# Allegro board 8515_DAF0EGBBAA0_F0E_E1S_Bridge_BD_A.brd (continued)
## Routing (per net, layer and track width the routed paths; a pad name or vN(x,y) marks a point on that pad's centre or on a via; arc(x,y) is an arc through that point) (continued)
DELTA_L_85_5INCH_TOP_DN: length 127
  TOP w0.132: J8.2 -14.43,31.48 -14.43,34.71 -14.64,35.89 -15.7,37.42 -18.96,38 -19.2,38.35 -19.08,39.03 -18.73,39.28 -14.55,38.54 -13.97,38.95 -13.8,39.91 -14.21,40.49 -19.01,41.34 -19.21,41.63 -19.08,42.36 -18.73,42.61 -14.55,41.87 -13.97,42.28 -13.8,43.23 -13.89,43.37 -13.95,43.46 -14.21,43.82 -18.92,44.65 -19.2,45.05 -19.08,45.69 -18.73,45.94 -16.65,45.57 -16.64,45.57 -14.55,45.2 -13.97,45.61 -13.88,46.09 -13.8,46.56 -14.21,47.15 -18.95,47.99 -19.2,48.35 -19.08,49.02 -18.73,49.27 -14.55,48.53 -13.97,48.94 -13.8,49.89 -14.21,50.48 -18.95,51.32 -19.2,51.68 -19.08,52.35 -18.73,52.6 -18.7,52.59 -14.55,51.86 -13.97,52.27 -13.8,53.22 -14.21,53.81 -18.96,54.65 -19.21,54.99 -19.08,55.68 -18.73,55.93 -14.55,55.19 -13.97,55.6 -13.8,56.55 -14.21,57.14 -18.96,57.98 -19.2,58.33 -19.09,59.01 -18.73,59.26 -14.55,58.52 -13.97,58.93 -13.8,59.88 -14.21,60.47 -18.97,61.31 -19.21,61.64 -19.08,62.34 -18.73,62.58 -14.54,61.85 -13.94,62.27 -13.8,63.09 -14.3,63.81 -18.98,64.64 -19.21,64.97 -19.08,65.7 -18.92,65.81 -18.76,65.92 -15.76,65.39 -14.66,66.16 -14.43,67.45 -14.43,72.53 J9.1
DELTA_L_85_5INCH_TOP_DP: length 127
  TOP w0.132: J8.1 -14.77,31.48 -14.77,34.68 -14.96,35.76 -15.9,37.11 -19.16,37.69 -19.56,38.27 -19.4,39.23 -18.81,39.64 -14.63,38.9 -14.28,39.15 -14.16,39.83 -14.4,40.18 -19.2,41.03 -19.57,41.55 -19.4,42.56 -18.81,42.97 -14.63,42.23 -14.28,42.48 -14.16,43.16 -14.4,43.51 -19.12,44.34 -19.56,44.97 -19.4,45.89 -18.81,46.3 -16.59,45.91 -16.58,45.9 -14.63,45.56 -14.28,45.81 -14.16,46.48 -14.4,46.84 -19.15,47.68 -19.56,48.27 -19.4,49.22 -18.81,49.63 -16.58,49.23 -14.63,48.89 -14.28,49.14 -14.16,49.81 -14.4,50.17 -19.15,51.01 -19.56,51.6 -19.4,52.55 -18.81,52.96 -18.53,52.91 -18.53,52.91 -14.63,52.22 -14.28,52.47 -14.16,53.14 -14.4,53.5 -19.16,54.34 -19.57,54.92 -19.4,55.88 -18.81,56.29 -14.63,55.55 -14.28,55.8 -14.16,56.47 -14.4,56.83 -19.16,57.66 -19.56,58.25 -19.4,59.21 -18.81,59.62 -14.63,58.88 -14.28,59.12 -14.16,59.8 -14.4,60.15 -19.17,61 -19.57,61.56 -19.4,62.53 -18.81,62.94 -14.62,62.21 -14.26,62.46 -14.16,63.02 -14.5,63.5 -19.17,64.33 -19.57,64.89 -19.54,65.03 -19.39,65.89 -18.84,66.28 -15.84,65.75 -14.97,66.36 -14.77,67.48 -14.77,72.53 J9.2
DELTA_L_85_10INCH_BOT_DN: length 254
  BOTTOM w0.132: J21.1 -20.16,102.88 -20.16,97.17 -20.36,96.04 -20.9,95.66 -24.28,96.25 -24.88,95.8 -25.05,94.85 -24.68,94.31 -19.69,93.43 -19.44,93.08 -19.56,92.4 -19.74,92.28 -19.74,92.27 -19.91,92.15 -24.29,92.92 -25,92.43 -25.14,91.64 -24.68,90.98 -19.69,90.1 -19.44,89.75 -19.56,89.07 -19.91,88.82 -24.33,89.6 -24.94,89.18 -25.1,88.28 -24.66,87.65 -19.69,86.77 -19.44,86.42 -19.56,85.74 -19.91,85.49 -23.86,86.19 -24.34,86.28 -24.93,85.87 -25.1,84.91 -24.69,84.33 -19.69,83.44 -19.44,83.09 -19.56,82.41 -19.91,82.16 -24.41,82.96 -24.92,82.6 -25.1,81.58 -24.69,81 -19.69,80.11 -19.44,79.76 -19.56,79.08 -19.91,78.83 -23.98,79.55 -24.41,79.63 -24.92,79.27 -25.1,78.23 -24.71,77.67 -19.69,76.78 -19.44,76.43 -19.5,76.09 -19.56,75.75 -19.91,75.51 -24.41,76.3 -24.92,75.94 -25.1,74.96 -24.66,74.33 -19.69,73.45 -19.44,73.1 -19.56,72.42 -19.91,72.18 -24.36,72.96 -24.93,72.56 -25.11,71.54 -24.74,71.02 -19.69,70.12 -19.44,69.77 -19.56,69.09 -19.91,68.85 -24.38,69.64 -24.93,69.25 -25.1,68.28 -24.67,67.68 -19.69,66.8 -19.44,66.44 -19.56,65.76 -19.91,65.52 -24.34,66.3 -24.93,65.88 -25.09,65.01 -24.62,64.34 -19.69,63.47 -19.44,63.11 -19.5,62.77 -19.56,62.44 -19.91,62.19 -24.43,62.99 -24.92,62.65 -25.1,61.64 -24.66,61.01 -19.69,60.14 -19.44,59.78 -19.56,59.11 -19.91,58.86 -24.33,59.64 -24.94,59.21 -25.1,58.31 -24.66,57.69 -19.69,56.81 -19.44,56.45 -19.56,55.78 -19.56,55.78 -19.91,55.53 -24.3,56.3 -24.94,55.85 -25.09,55.02 -24.62,54.35 -19.69,53.48 -19.44,53.12 -19.5,52.79 -19.56,52.45 -19.91,52.2 -24.32,52.98 -24.89,52.58 -25.06,51.64 -24.62,51.02 -19.69,50.15 -19.44,49.8 -19.5,49.46 -19.56,49.12 -19.91,48.87 -24.3,49.64 -24.86,49.25 -25.03,48.26 -24.63,47.69 -19.69,46.82 -19.44,46.47 -19.56,45.79 -19.91,45.54 -24.25,46.31 -24.88,45.86 -25.04,44.98 -24.61,44.36 -19.69,43.49 -19.44,43.14 -19.5,42.8 -19.56,42.46 -19.91,42.21 -24.42,43.01 -24.94,42.64 -25.11,41.66 -24.68,41.04 -19.69,40.16 -19.44,39.81 -19.56,39.13 -19.91,38.88 -24.68,39.72 -25.12,39.41 -25.32,38.29 -24.95,37.76 -21.17,37.09 -20.38,35.96 -20.16,34.68 -20.16,31.48 J22.2
DELTA_L_85_10INCH_BOT_DP: length 254
  BOTTOM w0.132: J22.1 -19.82,31.48 -19.82,34.71 -20.06,36.09 -20.97,37.4 -24.75,38.07 -24.96,38.37 -24.81,39.22 -24.6,39.36 -19.83,38.52 -19.25,38.93 -19.08,39.89 -19.49,40.47 -24.48,41.35 -24.75,41.74 -24.63,42.45 -24.34,42.65 -19.83,41.85 -19.25,42.26 -19.08,43.22 -19.49,43.8 -24.41,44.67 -24.68,45.06 -24.57,45.67 -24.17,45.95 -19.83,45.18 -19.54,45.39 -19.25,45.59 -19.08,46.55 -19.49,47.13 -24.43,48 -24.67,48.34 -24.54,49.05 -24.22,49.28 -19.83,48.51 -19.25,48.92 -19.08,49.87 -19.49,50.46 -24.42,51.33 -24.7,51.72 -24.58,52.38 -24.24,52.62 -19.83,51.84 -19.54,52.04 -19.25,52.25 -19.08,53.2 -19.49,53.79 -24.42,54.66 -24.73,55.1 -24.63,55.66 -24.22,55.94 -19.83,55.17 -19.25,55.58 -19.25,55.58 -19.08,56.53 -19.49,57.12 -24.46,58 -24.74,58.39 -24.63,59.01 -24.25,59.28 -19.83,58.5 -19.25,58.91 -19.08,59.86 -19.49,60.45 -24.46,61.33 -24.74,61.72 -24.61,62.45 -24.35,62.63 -19.83,61.83 -19.25,62.24 -19.08,63.19 -19.49,63.78 -24.42,64.65 -24.73,65.09 -24.62,65.69 -24.26,65.94 -19.83,65.16 -19.25,65.57 -19.08,66.52 -19.49,67.11 -24.47,67.99 -24.74,68.36 -24.62,69.05 -24.3,69.28 -19.83,68.49 -19.25,68.9 -19.08,69.85 -19.49,70.44 -24.55,71.33 -24.75,71.62 -24.62,72.36 -24.28,72.6 -19.83,71.82 -19.25,72.23 -19.08,73.18 -19.49,73.76 -24.46,74.64 -24.74,75.04 -24.61,75.74 -24.33,75.94 -19.83,75.15 -19.25,75.55 -19.08,76.51 -19.49,77.09 -24.51,77.98 -24.74,78.31 -24.61,79.08 -24.33,79.27 -19.83,78.47 -19.25,78.88 -19.08,79.84 -19.49,80.42 -24.49,81.31 -24.74,81.66 -24.61,82.4 -24.33,82.6 -19.83,81.8 -19.25,82.21 -19.08,83.17 -19.49,83.75 -24.49,84.64 -24.74,84.99 -24.62,85.67 -24.26,85.92 -19.83,85.13 -19.25,85.54 -19.08,86.5 -19.49,87.08 -24.46,87.96 -24.74,88.36 -24.63,88.98 -24.25,89.24 -19.83,88.46 -19.25,88.87 -19.08,89.83 -19.49,90.41 -24.48,91.29 -24.78,91.72 -24.69,92.23 -24.21,92.56 -19.83,91.79 -19.25,92.2 -19.08,93.16 -19.49,93.74 -24.48,94.62 -24.69,94.92 -24.57,95.61 -24.19,95.89 -20.82,95.3 -20.05,95.84 -19.82,97.14 -19.82,102.88 J21.2
DELTA_L_85_10INCH_IN1_DN: length 254
  IN1 w0.155: v3(-24.69,102.52) -24.89,102.32 -24.89,96.85 -25.42,96.08 -26.43,95.38 -29.25,95.88 -29.57,95.66 -29.69,94.96 -29.44,94.61 -24.4,93.72 -23.97,93.1 -24.14,92.1 -24.66,91.74 -29.43,92.58 -29.78,92.33 -29.88,91.75 -29.57,91.3 -24.56,90.42 -24.24,89.95 -24.15,89.83 -24.32,88.87 -24.91,88.45 -27.13,88.84 -29.35,89.24 -29.75,88.95 -29.85,88.38 -29.57,87.97 -24.54,87.09 -24.14,86.52 -24.32,85.53 -24.9,85.12 -29.35,85.91 -29.69,85.66 -29.81,84.99 -29.57,84.64 -24.56,83.76 -24.15,83.17 -24.35,82.07 -24.77,81.77 -29.35,82.58 -29.69,82.33 -29.81,81.66 -29.57,81.32 -24.56,80.43 -24.15,79.84 -24.33,78.84 -24.88,78.46 -29.35,79.25 -29.69,79 -29.81,78.33 -29.57,77.99 -24.56,77.1 -24.15,76.51 -24.32,75.55 -24.91,75.14 -29.35,75.92 -29.69,75.68 -29.81,75 -29.57,74.66 -24.56,73.77 -24.15,73.18 -24.32,72.22 -24.91,71.81 -29.35,72.59 -29.69,72.35 -29.81,71.67 -29.57,71.33 -24.56,70.44 -24.15,69.85 -24.32,68.89 -24.91,68.48 -29.35,69.26 -29.69,69.02 -29.81,68.35 -29.57,68 -24.56,67.11 -24.15,66.52 -24.32,65.56 -24.91,65.15 -29.35,65.93 -29.69,65.69 -29.81,65.02 -29.57,64.67 -24.56,63.79 -24.15,63.19 -24.32,62.23 -24.91,61.82 -29.35,62.6 -29.69,62.36 -29.81,61.69 -29.57,61.34 -24.56,60.46 -24.15,59.87 -24.32,58.9 -24.91,58.49 -29.35,59.27 -29.69,59.03 -29.81,58.36 -29.57,58.01 -24.63,57.14 -24.16,56.47 -24.3,55.7 -25.03,55.18 -29.35,55.94 -29.69,55.7 -29.81,55.03 -29.57,54.68 -24.56,53.8 -24.15,53.21 -24.32,52.24 -24.91,51.83 -29.35,52.61 -29.69,52.37 -29.81,51.7 -29.57,51.35 -24.56,50.47 -24.15,49.88 -24.32,48.92 -24.91,48.5 -29.35,49.28 -29.69,49.04 -29.81,48.37 -29.57,48.02 -24.56,47.14 -24.15,46.55 -24.32,45.59 -24.91,45.17 -29.35,45.96 -29.69,45.71 -29.81,45.04 -29.57,44.69 -24.56,43.81 -24.15,43.22 -24.32,42.26 -24.91,41.84 -29.35,42.63 -29.69,42.38 -29.79,41.82 -29.46,41.35 -24.5,40.47 -24.1,39.89 -24.26,38.97 -24.87,38.55 -29.41,39.36 -29.75,39.12 -29.88,38.37 -29.63,38.04 -26.33,37.45 -26.22,37.43 -25.34,36.56 -25.25,36.5 -25.23,36.45 -25.09,35.85 -24.92,35.12 -24.89,35.09 -24.89,32.04 v3(-24.69,31.85)
  BOTTOM w0.132: J24.2 v3(-24.69,102.52) ; J23.1 v3(-24.69,31.85)
DELTA_L_85_10INCH_IN1_DP: length 254
  IN1 w0.155: v3(-25.44,31.85) -25.25,32.04 -25.25,34.94 -25.44,35.77 -25.56,36.27 -26.4,37.1 -29.83,37.71 -30.27,38.27 -30.08,39.33 -29.49,39.74 -24.95,38.93 -24.59,39.18 -24.48,39.81 -24.71,40.14 -29.67,41.02 -30.17,41.74 -30.02,42.59 -29.43,43 -25,42.22 -24.65,42.47 -24.53,43.14 -24.77,43.48 -29.78,44.37 -30.19,44.96 -30.02,45.92 -29.43,46.33 -25,45.55 -24.65,45.79 -24.53,46.46 -24.77,46.81 -29.78,47.7 -30.19,48.29 -30.02,49.25 -29.43,49.66 -25,48.88 -24.65,49.12 -24.53,49.79 -24.77,50.14 -29.78,51.02 -30.19,51.62 -30.02,52.58 -29.43,52.99 -25,52.21 -24.65,52.45 -24.53,53.12 -24.77,53.47 -29.78,54.35 -30.19,54.94 -30.02,55.91 -29.43,56.32 -25.12,55.56 -24.63,55.9 -24.54,56.38 -24.84,56.81 -29.78,57.68 -30.19,58.27 -30.02,59.24 -29.43,59.65 -25,58.87 -24.65,59.11 -24.53,59.78 -24.77,60.13 -29.78,61.01 -30.19,61.6 -30.02,62.57 -29.43,62.98 -25,62.2 -24.65,62.44 -24.53,63.11 -24.77,63.46 -29.78,64.34 -30.19,64.93 -30.02,65.9 -29.43,66.31 -25,65.53 -24.65,65.77 -24.53,66.44 -24.77,66.79 -29.78,67.67 -30.19,68.26 -30.02,69.23 -29.43,69.64 -25,68.86 -24.65,69.1 -24.53,69.77 -24.77,70.12 -29.78,71 -30.19,71.59 -30.02,72.55 -29.43,72.97 -25,72.19 -24.65,72.43 -24.53,73.1 -24.77,73.45 -29.78,74.33 -30.19,74.92 -30.02,75.88 -29.43,76.3 -25,75.51 -24.65,75.76 -24.53,76.43 -24.77,76.78 -29.78,77.66 -30.19,78.25 -30.02,79.21 -29.43,79.63 -24.96,78.84 -24.65,79.05 -24.53,79.76 -24.77,80.1 -29.78,80.99 -30.19,81.58 -30.02,82.54 -29.43,82.96 -24.85,82.15 -24.67,82.27 -24.53,83.09 -24.77,83.43 -29.78,84.32 -30.19,84.91 -30.17,85.05 -30.02,85.87 -29.43,86.29 -24.99,85.5 -24.65,85.74 -24.52,86.43 -24.75,86.76 -29.78,87.65 -30.23,88.29 -30.08,89.16 -29.43,89.62 -25,88.83 -24.65,89.08 -24.53,89.74 -24.77,90.09 -29.78,90.98 -30.26,91.67 -30.11,92.54 -29.51,92.96 -24.75,92.12 -24.47,92.31 -24.35,93.01 -24.61,93.39 -29.65,94.28 -30.07,94.88 -29.89,95.87 -29.33,96.26 -26.51,95.76 -25.68,96.34 -25.25,96.96 -25.25,102.32 v3(-25.44,102.52)
  BOTTOM w0.132: J23.2 v3(-25.44,31.85) ; J24.1 v3(-25.44,102.52)
DELTA_L_85_10INCH_IN2_DN: length 254
  TOP w0.132: J26.2 v3(-22.9,102.52) ; J25.1 v3(-22.9,31.85)
  IN2 w0.155: v3(-22.9,31.85) -22.71,32.04 -22.71,34.95 -22.93,36.21 -23.51,37.05 -27.38,37.73 -27.59,38.03 -27.84,38.4 -27.68,39.29 -27.08,39.71 -22.57,38.91 -22.09,39.25 -21.99,39.81 -22.23,40.15 -27.24,41.04 -27.65,41.63 -27.48,42.59 -26.89,43 -22.46,42.22 -22.11,42.47 -21.99,43.14 -22.23,43.48 -27.24,44.37 -27.65,44.96 -27.48,45.92 -26.89,46.33 -22.46,45.55 -22.11,45.79 -21.99,46.46 -22.23,46.81 -27.24,47.7 -27.65,48.29 -27.48,49.25 -26.89,49.66 -22.46,48.88 -22.11,49.12 -21.99,49.79 -22.23,50.14 -27.24,51.02 -27.65,51.62 -27.48,52.58 -26.89,52.99 -22.46,52.21 -22.11,52.45 -21.99,53.12 -22.23,53.47 -27.24,54.35 -27.65,54.94 -27.48,55.91 -26.89,56.32 -22.43,55.53 -22.11,55.76 -21.99,56.45 -22.23,56.8 -27.24,57.68 -27.65,58.27 -27.48,59.24 -26.89,59.65 -22.46,58.87 -22.11,59.11 -21.99,59.78 -22.23,60.13 -27.24,61.01 -27.65,61.6 -27.48,62.57 -26.89,62.98 -22.46,62.2 -22.11,62.44 -21.99,63.11 -22.23,63.46 -27.24,64.34 -27.65,64.93 -27.48,65.9 -26.89,66.31 -22.46,65.53 -22.11,65.77 -21.99,66.44 -22.23,66.79 -27.24,67.67 -27.65,68.26 -27.48,69.23 -26.89,69.64 -22.46,68.86 -22.11,69.1 -21.99,69.77 -22.23,70.12 -27.24,71 -27.65,71.59 -27.48,72.55 -26.89,72.97 -22.46,72.19 -22.11,72.43 -21.99,73.1 -22.23,73.45 -27.24,74.33 -27.65,74.92 -27.48,75.88 -26.89,76.3 -22.46,75.51 -22.11,75.76 -21.99,76.43 -22.23,76.78 -27.24,77.66 -27.65,78.25 -27.48,79.21 -27.01,79.54 -26.89,79.63 -22.47,78.85 -22.1,79.11 -21.99,79.73 -22.26,80.11 -27.24,80.99 -27.65,81.58 -27.51,82.37 -27.51,82.52 -27.25,82.7 -26.89,82.96 -26.73,82.93 -26.05,82.81 -25.97,82.8 -25.87,82.79 -25.76,82.77 -22.45,82.22 -22.09,82.52 -21.99,83.06 -22.26,83.44 -27.24,84.32 -27.65,84.91 -27.48,85.87 -26.89,86.29 -22.48,85.51 -22.1,85.77 -21.98,86.45 -22.2,86.76 -27.24,87.65 -27.65,88.24 -27.48,89.2 -26.89,89.62 -22.46,88.83 -22.11,89.08 -21.99,89.74 -22.23,90.09 -27.24,90.98 -27.65,91.57 -27.57,92.05 -27.48,92.53 -26.9,92.94 -22.5,92.17 -22.14,92.37 -22,93.18 -22.16,93.41 -27.24,94.31 -27.65,94.9 -27.59,95.22 -27.59,95.24 -27.57,95.37 -27.54,95.5 -27.54,95.53 -27.53,95.59 -27.51,95.71 -27.5,95.76 -27.43,95.89 -27.28,96 -27.01,96.19 -26.89,96.27 -23.6,95.7 -22.88,96.34 -22.71,97.34 -22.71,102.32 v3(-22.9,102.52)
DELTA_L_85_10INCH_IN2_DP: length 254
  TOP w0.132: J25.2 v3(-22.15,31.85) ; J26.1 v3(-22.15,102.52)
  IN2 w0.155: v3(-22.15,31.85) -22.35,32.04 -22.35,34.98 -22.59,36.35 -23.3,37.38 -27.17,38.06 -27.29,38.23 -27.46,38.48 -27.35,39.08 -26.99,39.33 -22.49,38.53 -21.76,39.04 -21.61,39.89 -22.02,40.48 -27.03,41.36 -27.27,41.71 -27.15,42.38 -26.81,42.63 -22.37,41.84 -21.78,42.26 -21.61,43.22 -22.02,43.81 -27.03,44.69 -27.27,45.04 -27.15,45.71 -26.81,45.96 -22.37,45.17 -21.78,45.59 -21.61,46.55 -22.02,47.14 -27.03,48.02 -27.27,48.37 -27.15,49.04 -26.81,49.28 -22.37,48.5 -21.78,48.92 -21.61,49.88 -22.02,50.47 -27.03,51.35 -27.27,51.7 -27.15,52.37 -26.81,52.61 -22.37,51.83 -21.78,52.24 -21.61,53.21 -22.02,53.8 -27.03,54.68 -27.27,55.03 -27.15,55.7 -26.81,55.94 -22.35,55.16 -21.78,55.55 -21.61,56.54 -22.02,57.13 -27.03,58.01 -27.27,58.36 -27.15,59.03 -26.81,59.27 -22.37,58.49 -21.78,58.9 -21.61,59.87 -22.02,60.46 -27.03,61.34 -27.27,61.69 -27.15,62.36 -26.81,62.6 -22.37,61.82 -21.78,62.23 -21.61,63.19 -22.02,63.79 -27.03,64.67 -27.27,65.02 -27.15,65.69 -26.81,65.93 -22.37,65.15 -21.78,65.56 -21.61,66.52 -22.02,67.11 -27.03,68 -27.27,68.35 -27.15,69.02 -26.81,69.26 -22.37,68.48 -21.78,68.89 -21.61,69.85 -22.02,70.44 -27.03,71.33 -27.27,71.67 -27.15,72.35 -26.81,72.59 -22.37,71.81 -21.78,72.22 -21.61,73.18 -22.02,73.77 -27.03,74.66 -27.27,75 -27.15,75.68 -26.81,75.92 -22.37,75.14 -21.78,75.55 -21.61,76.51 -22.02,77.1 -27.03,77.99 -27.27,78.33 -27.15,79 -26.81,79.25 -22.39,78.47 -21.78,78.9 -21.62,79.81 -22.05,80.44 -27.03,81.32 -27.27,81.66 -27.15,82.33 -26.97,82.46 -26.81,82.58 -26.77,82.57 -26.76,82.57 -26.11,82.46 -26.03,82.45 -25.81,82.41 -25.81,82.41 -22.34,81.84 -21.76,82.33 -21.61,83.15 -22.05,83.77 -27.03,84.64 -27.27,84.99 -27.15,85.66 -26.81,85.91 -22.39,85.13 -21.78,85.56 -21.6,86.54 -21.99,87.08 -27.03,87.97 -27.27,88.32 -27.15,88.99 -26.81,89.24 -22.37,88.45 -21.78,88.87 -21.61,89.83 -22.02,90.42 -27.03,91.3 -27.27,91.65 -27.15,92.32 -26.81,92.56 -22.44,91.79 -21.82,92.14 -21.62,93.26 -21.96,93.74 -27.03,94.63 -27.27,94.98 -27.24,95.16 -27.24,95.17 -27.21,95.3 -27.19,95.42 -27.19,95.47 -27.18,95.52 -27.15,95.65 -27.15,95.65 -26.81,95.89 -23.49,95.32 -22.55,96.16 -22.35,97.31 -22.35,102.32 v3(-22.15,102.52)
DELTA_L_85_10INCH_TOP_DN: length 254
  TOP w0.132: J20.2 -27.44,31.48 -27.44,34.71 -27.69,36.18 -28.54,37.4 -32.11,38.03 -32.36,38.38 -32.24,39.06 -31.88,39.31 -27.45,38.52 -27.32,38.61 -26.87,38.93 -26.84,39.08 -26.7,39.89 -26.93,40.23 -26.99,40.31 -27.09,40.46 -29.6,40.9 -32.11,41.35 -32.36,41.71 -32.24,42.39 -31.89,42.64 -29.81,42.27 -27.45,41.85 -26.87,42.26 -26.7,43.22 -27.11,43.8 -32.15,44.69 -32.43,45.09 -32.31,45.75 -31.98,45.98 -27.45,45.18 -26.87,45.59 -26.71,46.52 -27.14,47.14 -32.16,48.02 -32.49,48.49 -32.38,49.09 -32.06,49.32 -27.45,48.51 -26.87,48.92 -26.71,49.82 -27.16,50.47 -32.1,51.34 -32.43,51.81 -32.33,52.37 -31.96,52.63 -27.45,51.84 -26.87,52.25 -26.71,53.16 -27.15,53.8 -32.09,54.67 -32.39,55.09 -32.27,55.74 -31.95,55.96 -27.45,55.17 -26.87,55.58 -26.79,56.03 -26.73,56.35 -26.71,56.49 -26.87,56.71 -27.07,57.01 -27.16,57.13 -27.36,57.16 -30.51,57.72 -32.1,58 -32.38,58.4 -32.26,59.05 -31.93,59.29 -27.45,58.5 -26.87,58.91 -26.7,59.86 -27.11,60.45 -32.12,61.33 -32.36,61.68 -32.24,62.36 -31.89,62.61 -29.81,62.24 -27.45,61.83 -26.87,62.24 -26.7,63.16 -27.14,63.78 -32.11,64.66 -32.12,64.67 -32.24,64.84 -32.36,65.01 -32.24,65.69 -31.89,65.94 -29.81,65.57 -27.45,65.16 -26.87,65.57 -26.71,66.48 -27.15,67.11 -32.11,67.99 -32.12,68 -32.18,68.09 -32.36,68.34 -32.24,69.02 -31.89,69.27 -29.81,68.9 -27.45,68.49 -26.87,68.9 -26.7,69.85 -27.13,70.47 -32.12,71.35 -32.36,71.69 -32.24,72.35 -31.89,72.6 -27.45,71.82 -26.87,72.23 -26.69,73.21 -27.08,73.76 -32.12,74.65 -32.36,75 -32.24,75.68 -31.89,75.93 -29.67,75.54 -27.45,75.15 -26.87,75.55 -26.71,76.43 -27.19,77.11 -32.02,77.96 -32.3,78.36 -32.17,79.06 -31.89,79.26 -27.45,78.47 -26.87,78.88 -26.7,79.86 -27.09,80.42 -31.95,81.28 -32.12,81.48 -32.25,81.66 -32.12,82.36 -31.82,82.57 -27.49,81.81 -27.01,82.15 -26.98,82.17 -26.86,82.25 -26.85,82.3 -26.81,82.53 -26.8,82.61 -26.75,82.89 -26.7,83.17 -26.95,83.53 -27.11,83.75 -29.47,84.17 -32.11,84.64 -32.36,84.99 -32.24,85.67 -31.89,85.92 -29.95,85.57 -27.45,85.13 -26.87,85.54 -26.69,86.53 -27.08,87.08 -32.11,87.97 -32.24,88.14 -32.36,88.32 -32.24,89 -31.89,89.25 -27.47,88.46 -26.87,88.89 -26.7,89.84 -27.1,90.42 -32.11,91.3 -32.36,91.65 -32.24,92.33 -31.89,92.57 -27.48,91.8 -26.86,92.23 -26.71,93.1 -27.17,93.75 -32.11,94.62 -32.12,94.64 -32.36,94.98 -32.24,95.66 -31.89,95.9 -28.39,95.29 -27.64,95.81 -27.44,96.98 -27.44,102.88 J19.1
DELTA_L_85_10INCH_TOP_DP: length 254
  TOP w0.132: J19.2 -27.78,102.88 -27.78,97.01 -27.95,96.01 -28.47,95.65 -31.97,96.26 -32.55,95.85 -32.72,94.9 -32.39,94.42 -32.28,94.31 -27.37,93.44 -27.07,93.02 -27.17,92.43 -27.56,92.16 -31.97,92.93 -32.55,92.53 -32.72,91.57 -32.31,90.98 -27.3,90.1 -27.06,89.76 -27.18,89.08 -27.55,88.82 -31.97,89.61 -32.55,89.2 -32.72,88.24 -32.31,87.66 -27.28,86.77 -27.05,86.45 -27.18,85.74 -27.53,85.49 -29.89,85.91 -31.97,86.28 -32.55,85.87 -32.72,84.91 -32.39,84.44 -32.31,84.33 -32.17,84.3 -29.53,83.84 -27.31,83.44 -27.06,83.09 -27.08,82.95 -27.13,82.67 -27.17,82.45 -27.2,82.43 -27.57,82.17 -31.9,82.93 -32.43,82.56 -32.61,81.57 -32.39,81.28 -32.14,80.97 -27.28,80.11 -27.06,79.78 -27.18,79.08 -27.53,78.83 -31.97,79.62 -32.48,79.26 -32.66,78.28 -32.22,77.65 -27.39,76.8 -27.07,76.35 -27.18,75.75 -27.53,75.51 -29.61,75.87 -31.97,76.29 -32.55,75.88 -32.72,74.92 -32.31,74.34 -27.28,73.45 -27.05,73.13 -27.18,72.42 -27.53,72.18 -31.97,72.96 -32.55,72.55 -32.72,71.61 -32.32,71.04 -27.33,70.16 -27.06,69.77 -27.18,69.09 -27.53,68.85 -29.75,69.24 -31.97,69.63 -32.55,69.22 -32.72,68.26 -32.46,67.89 -32.38,67.78 -32.28,67.67 -27.35,66.8 -27.07,66.4 -27.18,65.76 -27.53,65.52 -29.75,65.91 -31.97,66.3 -32.55,65.89 -32.72,64.93 -32.52,64.64 -32.38,64.45 -32.28,64.34 -27.34,63.47 -27.06,63.08 -27.18,62.44 -27.53,62.19 -29.75,62.58 -31.97,62.97 -32.55,62.56 -32.72,61.6 -32.71,61.59 -32.31,61.02 -27.31,60.14 -27.06,59.78 -27.18,59.11 -27.53,58.86 -32.01,59.65 -32.57,59.25 -32.74,58.32 -32.3,57.69 -30.85,57.43 -27.42,56.83 -27.35,56.82 -27.07,56.41 -27.12,56.09 -27.18,55.78 -27.53,55.53 -32.03,56.32 -32.59,55.93 -32.75,55.01 -32.29,54.36 -27.35,53.49 -27.07,53.08 -27.18,52.45 -27.53,52.2 -32.04,52.99 -32.64,52.57 -32.79,51.73 -32.3,51.03 -27.36,50.16 -27.07,49.74 -27.18,49.12 -27.53,48.87 -32.14,49.68 -32.69,49.29 -32.85,48.41 -32.36,47.71 -27.34,46.83 -27.06,46.44 -27.07,46.44 -27.18,45.79 -27.53,45.54 -32.06,46.34 -32.62,45.94 -32.79,45.01 -32.35,44.38 -27.31,43.49 -27.06,43.14 -27.18,42.46 -27.53,42.21 -29.75,42.6 -31.97,43 -32.55,42.59 -32.72,41.63 -32.71,41.61 -32.3,41.03 -29.66,40.57 -27.29,40.15 -27.27,40.12 -27.06,39.82 -27.18,39.14 -27.18,39.13 -27.52,38.89 -27.53,38.88 -31.96,39.67 -32.55,39.26 -32.72,38.3 -32.31,37.72 -28.74,37.09 -28.02,36.04 -27.78,34.68 -27.78,31.48 J20.1
DUALPORT_N_E1S_0: length 6.7
  TOP w0.381: v2(22.03,40.81) 23.01,40.81 R213.2 23.81,40.43 24.61,39.63 R214.2 25.38,39.63 25.45,39.69 J4.B9
DUALPORT_N_E1S_1: length 3.8
  TOP w0.109: R229.2 R228.2 51.59,39.8 v3(52.09,39.8) 52.79,39.8 52.89,39.7 J5.B9
DUALPORT_N_E1S_2: length 6.2
  TOP w0.254: R244.2 75.31,38.29 74.84,37.83 v2(74.84,36.83)
  TOP w0.381: R243.2 77.4,39.7 J6.B9
  TOP w0.508: R244.2 75.67,38.33 76.35,39.01 R243.2
DUALPORT_N_E1S_3: length 8.2
  TOP w0.381: J7.B9 103.91,39.7 103.47,39.26 R258.2
  TOP w0.508: R259.2 99.89,36.62 v2(99.89,37.15) 99.86,37.17 99.86,37.89 99.96,37.99 99.96,38 100.83,38.87 101.19,39.22 101.19,39.22 101.24,39.26 R258.2
FM_AUX_PWR_EN: length 136
  TOP w0.109: v3(26.47,15.9) 26.42,15.85 26.42,15.36 27.03,13.89 27.23,13.69 27.23,13.34 26.74,12.85 R15.1 ; U35.P6 v4(125.02,33.7)
  IN1 w0.124: v3(26.47,15.9) 26.85,16.28 27.75,16.28 28.26,16.78 34.18,16.78 35.87,15.09 39.81,11.14 55,11.14 55.82,10.32 98.03,10.32 98.81,11.1 105.72,11.1 106,10.83 107.02,10.83 109.99,13.8 112.89,13.8 112.99,13.9 118.93,13.9 120.22,15.19 120.22,17.77 122.05,19.6 124.27,19.6 127.87,23.2 127.87,29.21 127.04,30.04 126.28,30.04 124.62,31.7 124.62,33.13 125.02,33.52 v4(125.02,33.7)
  BOTTOM w0.109: v4(125.02,33.7) 125.18,33.7 125.46,33.42 125.46,32.75 125.65,32.56 125.65,31.14 125.45,30.95 125.45,30.11 124.86,29.51 124.86,28.14 v1(124.8,28.09) PR76.1
FM_AUX_PWR_EN_R: length 11.1
  TOP w0.109: GF1.B12 26.45,4.1 26.8,4.45 v2(26.8,10.67) 26.8,11.23 26.62,11.41 R15.2 26.64,12.07 27.51,12.07 R4607.2
FM_AUX_PWR_RST_EN: length 98.7
  TOP w0.109: v5(27.09,15.41) 27.09,14.87 27.71,14.25 27.71,13.02 R4607.1
  IN1 w0.124: v5(27.09,15.41) 27.58,15.9 27.91,15.9 28.41,16.4 34.02,16.4 39.66,10.76 54.84,10.76 55.75,9.86 98.13,9.86 98.99,10.72 105.56,10.72 105.84,10.45 107.17,10.45 107.56,10.84 108.45,10.84 110.66,13.04 113.21,13.04 113.31,13.14 116.75,13.14 v3(117.17,12.73)
  BOTTOM w0.109: v3(117.17,12.73) 116.7,13.2 U46.2
FM_BOARD_ID_0: length 5.6
  TOP w0.109: U35.R5 v4(124.22,32.9)
  BOTTOM w0.109: 125.08,31.25 125.08,31.25 124.89,31.06 124.89,30.23 124.78,30.12 R738.2 124.11,29.9 123.54,29.9 R790.1 ; 125.08,31.25 v1(125.07,31.25) ; 125.08,31.25 125.08,32.17 124.35,32.9 v4(124.22,32.9)
FM_BOARD_ID_1: length 4.7
  TOP w0.109: U35.T4 v4(124.22,32.1)
  BOTTOM w0.109: v4(124.22,32.1) 124.22,31.62 123.61,31.02 123.1,31.02 122.3,30.23 R735.1 R737.2
FM_BOARD_ID_2: length 8.2
  TOP w0.109: U35.P7 v4(125.82,33.7)
  BOTTOM w0.109: R734.1 126.87,27.79 126.87,28.88 126.43,29.32 R791.2 126.36,29.36 126.95,29.95 126.95,30.42 127,30.48 127,32.28 126.18,33.1 126.18,33.34 v4(125.82,33.7)
FM_BOARD_ID_3: length 12.5
  TOP w0.109: U35.N6 v4(125.02,34.5)
  BOTTOM w0.109: v4(125.02,34.5) 125.02,34.34 124.59,33.91 124.59,33.4 124.46,33.27 123.95,33.27 123.75,33.07 123.75,31.65 123.47,31.37 123,31.37 122.5,30.87 121.86,30.87 120.44,30.29 120.27,30.12 R736.2 120.75,29.64 120.75,28.4 121.42,27.73 v1(121.42,27.65) 120.71,27.65 R733.1
FM_BOARD_REV_ID0: length 13
  TOP w0.109: R283.1 R284.2 138.25,51.85 138.25,47.64 137.51,45.84 137.1,45.43 136.61,45.43 v4(134.09,42.9) U35.C16
FM_BOARD_REV_ID1: length 4
  TOP w0.109: U35.D16 134.43,42.1 134.8,42.47 v4(135.17,42.47) 135.17,42.23 R282.1 R285.2
FM_BOARD_REV_ID2: length 4.7
  TOP w0.109: U35.D15 v4(133.03,42.52) 134.39,42.52 134.89,43.01 135.4,43.01 R506.1 R505.2
FM_CARD_TYPE: length 183.5
  TOP w0.109: U35.B2 v4(121.82,44.1)
  IN1 w0.124: v3(13.8,15.11) 15.37,15.11 15.88,14.61 19.97,14.61 20.45,15.09 20.45,19.15 25.35,24.05 32.31,24.05 35.46,27.2 35.46,27.76 37.19,29.49 37.19,30.4 36.6,30.99 36.6,31.78 36.93,32.11 42.24,32.11 43.48,30.86 48.05,30.86 51.88,27.03 54.4,27.03 55.29,27.91 58.05,27.91 60.21,25.75 62.48,25.75 62.79,25.44 62.79,23.82 64.25,22.37 64.63,22.37 64.83,22.56 71.33,22.56 73.1,24.33 77.27,24.33 80.75,27.82 81.92,27.82 82.64,27.1 82.64,26.39 83.53,25.49 85.32,25.49 90.85,31.02 94.16,31.02 95.07,30.11 100.18,30.11 103.27,27.02 104.13,27.02 104.83,27.72 108.31,27.72 110.24,25.79 110.24,24.69 111.34,23.59 113.46,23.59 113.73,23.87 117.39,23.87 118.08,24.56 118.86,24.56 119.09,24.33 121.83,24.33 122.06,24.56 123.04,24.56 124.84,26.37 124.84,27.13 124.64,27.33 123.72,27.33 123.39,27.66 119.42,27.66 118.37,27.23 117.12,27.23 116.56,27.46 115.77,28.24 115.77,29.08 115.97,29.27 116.67,29.27 116.87,29.08 116.87,28.5 117.17,28.19 118.31,28.19 118.57,28.3 118.72,28.45 118.72,31.09 119.41,31.78 121.23,31.78 121.75,32.29 122.94,32.29 123.4,31.84 v4(123.39,31.84)
  IN2 w0.124: v4(121.82,44.1) 120.53,42.81 120.53,36.77 121.36,35.94 121.36,35.18 121.67,34.87 123.68,34.87 123.8,34.75 123.8,32.24 123.4,31.84 v4(123.39,31.84)
  BOTTOM w0.109: v3(13.8,15.11) 13.8,14.06 13.6,13.85 13.6,11.74 R10.2
FM_CLKBUF_EN: length 149
  TOP w0.109: R476.2 37.72,31.61 v3(37.35,31.24) ; R477.1 36.73,31.86 v3(37.35,31.24) ; v3(37.35,31.24) 37.62,31.24 38.12,30.74 U32.31
  IN1 w0.124: v3(108.24,11.34) 110.32,13.42 113.05,13.42 113.15,13.52 119.08,13.52 120.6,15.03 120.6,17.4 122.42,19.22 124.63,19.22 130.39,24.98 131.96,24.98 132.97,26 132.97,26.69 133.18,26.9 133.63,26.9 134.08,26.46 136.15,26.46 136.92,25.68 138.38,25.68 139.04,25.02 140.37,25.02 141.78,26.43 141.78,28.38 141.25,28.91 141.25,30.74 142.49,31.98 142.49,35.18 141.91,35.76 141.45,35.76 140.44,36.78 137.61,36.78 v3(137.24,37.16)
  IN2 w0.124: v3(37.35,31.24) 38.9,29.68 40.91,29.68 41.3,29.3 41.3,27.34 43.91,24.73 47.18,24.73 60.89,11.02 60.91,11.02 61,10.94 61.07,10.94 61.08,10.92 85.74,10.92 86.24,10.42 97.14,10.42 97.83,11.11 108.02,11.11 v3(108.24,11.34)
  BOTTOM w0.109: R626.1 134.49,40.5 136.56,40.5 137.13,39.92 137.13,39.43 137.24,39.33 v3(137.24,37.16)
FM_CLKBUF_R_EN: length 1.6
  TOP w0.109: U35.F14 v4(132.22,40.9)
  BOTTOM w0.109: v4(132.22,40.9) 132.87,40.9 132.87,40.9 R626.2
FM_FRU_WC_N: length 29.6
  TOP w0.109: R276.1 117.35,57.51 117.35,55.59 117.08,55.32 117.08,53.71 115.5,52.14 115.5,50.39 113.69,48.58 113.69,47.5 114.67,46.52 115.5,46.52 116.62,45.39 116.62,44.6 116.63,44.59 116.63,44.57 117.5,43.7 v3(117.58,43.7) ; v4(120.58,35.32) 120.58,35.32 120.58,35.33 121.04,35.33 U35.M1
  IN2 w0.124: v3(117.58,43.7) 117.58,41.99 118.39,41.18 118.39,35.84 118.9,35.33 120.58,35.33 120.58,35.32 v4(120.58,35.32)
FM_FRU_WC_N_R: length 4.2
  TOP w0.109: U15.7 120.66,58.95 120.64,58.93 v3(120.42,58.93) 120.29,58.93 119.89,59.33 R414.1 R417.1 118.21,59.33 117.73,58.85 R276.2
FM_MB_SLOT_ID0: length 178.8
  TOP w0.109: U15.2 125.78,58.95 125.3,59.43 124.74,59.43 v3(124.26,58.94) ; U35.R7 v4(125.82,32.9) ; R8.1 v3(15.9,13.61)
  IN1 w0.124: v3(114.45,22.06) 113.14,22.06 112.46,21.38 110.79,21.38 110.29,21.87 105.24,21.87 98.69,28.43 94.88,28.43 94.15,27.69 89.92,27.69 84.86,22.64 73.77,22.64 72.02,20.89 65.52,20.89 65.33,20.7 63.55,20.7 62.28,21.97 52.99,21.97 49.82,25.15 44.32,25.15 42.52,23.35 37.44,23.35 35.28,21.18 25.17,21.18 22.23,18.24 22.23,14.3 20.09,12.17 17.35,12.17 v3(15.9,13.61)
  IN2 w0.124: v4(125.82,32.9) 125.43,33.29 125.43,38.09 124.63,38.89 124.63,40.73 124.63,40.73 124.63,41.07 124.63,41.07 124.63,46.9 124.71,46.98 124.71,49.36 125.73,50.38 125.73,51.26 126.61,52.13 126.61,53.7 126.25,54.06 126.25,54.72 v3(127.09,55.57)
  BOTTOM w0.109: v3(127.09,55.57) 127.51,55.98 127.51,57.04 128.18,57.72 128.18,59.41 127.88,59.71 R280.1 R274.2 125.62,59.82 125.13,59.82 v3(124.26,58.94) ; v4(125.82,32.9) 125.95,32.76 125.95,30.97 125.82,30.83 125.82,26.37 126.77,25.41 126.77,22.71 126.46,22.4 125.7,22.4 125.48,22.61 125.48,23.28 124.64,24.12 120.86,24.12 119.61,22.88 119.61,22.67 117.38,20.44 116.07,20.44 v3(114.45,22.06)
FM_MB_SLOT_ID1: length 194.9
  TOP w0.109: U15.3 125.2,60.22 v3(124.33,61.09) ; U35.P11 v4(129.82,33.7)
  IN1 w0.124: v3(13.28,14.58) 15.29,14.58 15.67,14.2 20.14,14.2 20.9,14.96 20.9,18.9 25.63,23.62 32.44,23.62 35.84,27.02 35.84,27.61 38.03,29.79 40.69,29.79 41.4,30.51 43.26,30.51 43.43,30.33 46.46,30.33 52.79,23.99 61.5,23.99 62.02,23.48 62.6,23.48 64.09,21.99 64.79,21.99 64.98,22.18 71.48,22.18 73.23,23.93 84.33,23.93 91.04,30.64 94,30.64 94.91,29.73 99.39,29.73 105.12,24 110.37,24 111.2,23.17 113.38,23.17 v3(113.69,22.86)
  IN2 w0.124: v3(128.04,55.73) 127.87,55.55 127.87,54.35 129.83,52.38 129.83,50.75 130.04,50.54 130.04,48.22 130.24,48.02 130.24,34.12 v4(129.82,33.7)
  BOTTOM w0.109: v4(129.82,33.7) 129.82,33.58 130.2,33.2 130.2,31.11 130.96,30.35 130.96,25.45 130.21,24.7 130.21,23.6 130.66,23.16 130.66,21.89 129.86,21.09 124.22,21.09 123.16,22.15 121.57,22.15 120.27,20.85 120.27,20.68 119.55,19.96 118.53,19.96 117.5,18.92 115.91,18.92 113.92,20.91 113.92,22.63 v3(113.69,22.86) ; R6.2 11.31,12.97 10.87,13.41 10.87,14.3 v1(11.05,14.48) 11.15,14.58 v3(13.28,14.58) ; v3(124.33,61.09) 124.92,60.5 125.29,60.5 R273.2 R279.1 126.83,60.94 127.55,60.23 128.04,60.23 128.57,59.7 128.57,57.57 127.87,56.87 127.87,55.9 v3(128.04,55.73)
FM_P3V3_E1S_0_EN: length 181.6
  TOP w0.109: Q9.2 7.57,36.6 7.44,36.73 6.85,36.73 R4640.1 R4643.1 6.75,38.12 v3(6.87,38.24)
  IN1 w0.124: v3(107.19,38.67) 107.19,38.44 106.93,38.18 106.04,38.18 102.61,41.61 96.61,41.61 95.73,42.49 94.44,42.49 91.79,45.14 86.18,45.14 83.43,42.39 79.47,42.39 78.05,40.97 75.08,40.97 73.76,39.65 73.76,37.59 72.9,36.73 72.9,35.15 71.88,34.14 67.54,34.14 62.64,39.04 60.58,39.04 58.47,41.15 56.11,41.15 54.56,42.7 50.47,42.7 49.96,42.19 49.96,34.77 49.17,33.99 44.25,33.99 43.23,35 37.97,35 37.16,35.81 37.16,36.73 36.35,37.54 33.71,37.54 33.05,36.88 32.49,36.88 30,39.37 24.21,39.37 23.77,38.94 17.02,38.94 16.43,38.35 16.43,38.2 15.39,37.16 12.22,37.16 11.05,38.33 6.96,38.33 v3(6.87,38.24) ; v3(125.04,56.39) 125.05,56.39 125.05,56.55 124.39,57.21 123.85,57.21 123.73,57.34 123.73,58.23 123.61,58.36 123.58,58.36 123.58,58.54 123.02,59.11 121.31,59.11 120.58,58.37 119.44,58.37 119.1,58.03 119.1,57.55 118.54,56.99 117.67,54.87 114.42,51.62 114.42,49.13 112.2,46.91 112.2,45.87 113,45.07 v3(115.13,45.07)
  IN2 w0.124: v3(115.13,45.07) 115.13,45.07 115.13,45.07 115.13,45.07 115.32,44.88 115.32,41.03 114.02,39.74 111.49,39.74 111.05,40.17 110.38,40.17 108.32,38.12 107.74,38.12 v3(107.19,38.67)
  BOTTOM w0.109: v3(125.04,56.39) 125.05,56.39 125.05,56.21 126.16,55.09 127.24,55.09 128.62,53.72 128.62,53.58 129.04,53.15 129.04,50.54 128.28,49.78 128.28,48.77 128.02,48.51 128.02,48.24 127.54,47.77 R633.2
FM_P3V3_E1S_0_EN_D: length 2.8
  TOP w0.109: Q9.3 7.46,35.95 v3(7.26,36.14) 6.83,35.71 R4642.2 5.95,36.51 R4640.2
FM_P3V3_E1S_0_EN_G: length 1.7
  TOP w0.109: Q9.5 9.97,36.58 10.31,36.58 v3(10.74,37.01) 11.18,36.58 R4641.1
FM_P3V3_E1S_0_EN_R_G: length 5.6
  TOP w0.109: C319.1 R4641.2 12.08,36.67 11.28,37.47 R4639.2 11.28,37.49 11.1,37.67 9.2,37.67 9.1,37.56 v3(9.1,37.28) 9.12,37.25 Q9.6
FM_P3V3_E1S_0_R_EN: length 4.8
  TOP w0.109: U35.C9 v4(128.22,43.3)
  BOTTOM w0.109: R633.1 127.51,46.74 127.78,46.46 v1(128.13,45.64) 128.6,45.17 128.6,43.83 128.22,43.45 v4(128.22,43.3)
FM_P3V3_E1S_0_SW_EN: length 33.8
  TOP w0.109: v3(12.45,45.85) 12.32,45.72 R190.2 R195.1 12.04,44.7 13,45.67 U7.2 ; v3(16.89,37.93) R491.1 16.12,38.84 15.43,39.54 U26.D2 ; R4642.1 v3(5.95,35.05)
  IN1 w0.124: v3(5.95,35.05) 6.39,35.48 7.67,35.48 8.66,36.47 9.32,36.47 10.39,37.54 11.3,37.54 12.06,36.78 15.55,36.78 16.31,37.54 16.43,37.54 16.83,37.93 v3(16.89,37.93)
  IN2 w0.124: v3(12.45,45.85) 13.13,45.16 13.13,43.26 12.34,42.47 12.34,41.27 12.36,41.25 12.36,39.3 13.03,38.64 16.18,38.64 v3(16.89,37.93)
  BOTTOM w0.109: v3(12.45,45.85) 12.09,46.2 R454.2
FM_P3V3_E1S_1_EN: length 135.1
  IN1 w0.124: v3(124.39,56.44) 124.14,56.69 123.57,56.69 123.21,57.05 123.21,58.38 122.86,58.73 121.47,58.73 119.98,57.24 119.79,57.16 119.39,57.16 118.79,56.56 117.97,54.59 115.01,51.62 115.01,47.21 114.06,46.26 v3(112.84,46.26) ; v3(89.62,39) 89.62,40.35 90.3,41.03 95,41.03 96.37,39.66 96.84,39.66 97.86,40.68 102.9,40.68 105.77,37.81 107.55,37.81 108.08,38.34 v3(108.08,38.66)
  IN2 w0.124: v3(108.08,38.66) 108.08,38.66 108.26,38.66 110.18,40.58 111.52,40.58 111.92,40.19 113.84,40.19 114.89,41.23 114.89,44.21 v3(112.84,46.26)
  BOTTOM w0.109: R685.2 126.39,47.77 126.97,48.36 126.97,49 128.05,50.08 128.05,51.58 127.82,51.81 127.37,51.81 127.16,52.02 127.16,53.14 127.46,53.44 127.46,54.32 127.08,54.7 125.89,54.7 124.39,56.2 v3(124.39,56.44) ; Q10.2 48.69,43.61 47.47,44.83 R4645.1 R4648.1 45.49,46.07 45.75,46.33 46.89,46.33 48.98,44.24 49.84,44.24 51.97,42.11 51.97,41.91 54.61,39.27 56.31,39.27 56.67,39.62 58.75,39.62 59.26,39.12 61.5,39.12 65.74,34.87 68.72,34.87 68.73,34.87 69.39,35.15 71.34,35.53 72.54,35.53 80.4,43.4 81.67,43.4 82.32,42.75 83.31,42.75 85.55,44.98 88.01,44.98 89.74,43.26 89.74,40.34 89.62,40.22 v3(89.62,39)
FM_P3V3_E1S_1_EN_D: length 6.3
  BOTTOM w0.109: R4645.2 44.68,44.71 R4647.2 45.5,43.52 45.8,43.23 v1(46.74,43.23) 47.5,42.47 49.03,42.47 49.34,42.78 Q10.3
FM_P3V3_E1S_1_EN_G: length 4
  BOTTOM w0.109: Q10.5 48.69,41.83 48.58,41.94 46.76,41.94 v1(46.74,41.96) 46.31,42.39 R4646.1
FM_P3V3_E1S_1_EN_R_G: length 4.8
  BOTTOM w0.109: R4646.2 45.61,41.59 C320.1 R4644.2 46.64,40.59 v1(46.74,40.69) 47.21,41.16 Q10.6
FM_P3V3_E1S_1_R_EN: length 6.2
  TOP w0.109: U35.D9 v4(128.22,42.5)
  BOTTOM w0.109: R685.1 126.76,46.97 127.46,46.28 127.59,45.96 127.59,44.71 v1(128.11,44.19) 127.83,43.9 127.83,42.88 v4(128.22,42.5)
FM_P3V3_E1S_1_SW_EN: length 33.4
  TOP w0.109: v3(45.01,36.35) 45.01,36.6 44.15,37.46 U27.D2 ; U8.2 41.45,43.61 41.4,43.56 v3(41.2,43.56) 40.53,43.56 R194.2
  IN1 w0.124: v3(45.01,36.35) 44.81,36.14 44.81,34.85 44.93,34.72 48.41,34.72 48.67,34.98 48.67,39.74 v3(49.26,40.34) 49.29,40.34 49.29,41.7 46.57,44.42 42.11,44.42 41.88,44.18 41.82,44.18 v3(41.2,43.56)
  BOTTOM w0.109: R4647.1 44.27,43.46 44.27,43.1 43.84,42.67 43.08,42.67 42.98,42.77 42.98,43.31 R196.1 42.73,43.56 v3(41.2,43.56) 41.02,43.56 40.72,43.27 40.72,42.99 v1(40.76,42.95) 40.87,42.84 R456.2 ; v3(45.01,36.35) 45.01,36.77 R495.1
FM_P3V3_E1S_2_EN: length 119.3
  TOP w0.109: v4(126.36,48.39) R634.2 ; v3(64.68,19.32) 63.8,19.32 63.41,19.7 63.41,19.88 R4653.1 R4650.1 62.6,19.78 61.4,19.78 60.92,19.3 60.47,19.3 60.34,19.16 Q11.2
  IN1 w0.124: v3(59.45,17.72) 59.82,17.35 61.09,17.35 61.79,16.66 72.03,16.66 75.21,19.84 86.07,19.84 89.9,23.67 93.14,23.67 94.86,21.96 100.53,21.96 103.96,18.53 106.53,18.53 107.86,17.2 109.78,17.2 110.75,16.23 112.61,16.23 113.2,16.82 115.34,16.82 118.76,20.24 119.38,20.24 120.14,21 122.22,21 122.75,20.46 123.3,20.46 125.22,22.38 125.22,23.8 126.85,25.43 126.85,27.07 125.85,28.07 125.85,28.96 124.32,30.49 v4(123.81,30.49)
  IN2 w0.124: v4(126.36,48.39) 126.33,48.39 125.41,47.47 125.41,38.8 126.21,38 126.21,33.84 126.35,33.69 126.35,32.78 125.78,32.2 125.78,31.09 125.17,30.49 v4(123.81,30.49) ; v3(64.68,19.32) 61.05,19.32 v3(59.45,17.72)
FM_P3V3_E1S_2_EN_D: length 2.5
  TOP w0.109: 62.26,19.29 R4650.2 ; 62.26,19.29 R4652.2 ; 62.26,19.29 v3(61.64,18.67) 61.56,18.58 Q11.3
FM_P3V3_E1S_2_EN_G: length 6.7
  TOP w0.109: R4651.1 61.1,24.56 61.21,24.45 61.21,22.24 61.47,21.99 62,21.99 62.15,21.84 v2(62.15,21.44) 60.81,21.44 60.34,20.97 Q11.5
FM_P3V3_E1S_2_EN_R_G: length 5.4
  TOP w0.109: R4651.2 60.76,23.2 R4649.2 C321.1 60.27,21.58 59.69,21.01 Q11.6 58.96,20.48 v2(58.28,21.16)
FM_P3V3_E1S_2_R_EN: length 2.7
  TOP w0.109: R634.1 126.36,46.81 126.63,46.54 126.63,44.88 U35.A8
FM_P3V3_E1S_2_SW_EN: length 196
  TOP w0.109: R4652.1 63.31,18.65 64.26,18.65 65.37,19.11 67.12,19.11 67.61,19.6 v3(67.61,20.02) 67.02,20.62 U28.D2 ; U10.2 62.34,26.74 R201.2 R204.1 v3(60.91,26.47) 58.75,26.47 58.19,25.91 58.19,24.6 57.45,23.86 57.45,21.15 58.79,19.8 58.79,18 57.84,15.57 56.22,13.81 55.75,13.14 55.75,11.73 54.31,10.29 54.28,10.29 54.28,10.3 v3(54.27,10.3)
  IN1 w0.124: v3(54.27,10.3) 54.28,10.3 54.28,10.29 54.64,10.29 55.46,9.46 98.39,9.46 99.28,10.35 105.41,10.35 105.68,10.07 107.33,10.07 107.72,10.46 108.61,10.46 110.81,12.66 113.36,12.66 113.46,12.76 115.93,12.76 117.09,11.6 117.09,11.6 119.32,9.36 131.52,9.36 132.87,9.92 133.99,11.04 133.99,15.78 134.87,16.66 134.87,20.08 134.25,20.7 134.25,21.73 132.76,23.23 132.76,24.19 133.04,24.47 133.86,24.47 135.44,22.89 138.43,22.89 138.59,23.06 138.59,23.32 139.35,24.08 140.76,24.08 142.71,26.04 142.71,30.58 143.55,31.41 143.55,35.19 144.21,35.85 144.21,37.93 143.06,39.09 139.85,39.09 138.28,40.65 138.28,50.66 139.05,52.52 139.05,55.75 139.2,55.9 139.2,56.71 v3(138.73,57.17)
  BOTTOM w0.109: v3(67.61,20.02) 67.76,20.17 67.76,21.17 R498.1 R458.2 67.08,21.51 67.08,24.74 65.2,26.62 61.06,26.62 v3(60.91,26.47) ; v3(138.73,57.17) 138.55,56.98 v3(135.25,56.98)
FM_P3V3_E1S_3_EN: length 62.3
  IN1 w0.124: v3(116.41,26.98) 112.07,31.32 110.22,31.32 109.83,31.71 108.79,31.71 108.41,31.34 108.05,31.34 107.25,32.14 106.03,32.14 105.66,31.77 104.18,31.77 103.8,31.39 95.55,31.39 94.55,32.39 94.01,32.39 91.17,35.23 90.63,35.23 89.29,36.57 81.2,36.57 80.57,35.95 80.57,33.42 81.97,32.02 81.97,29.64 83.59,28.02 83.69,28.02 v3(84.76,26.95)
  BOTTOM w0.109: R728.2 116.47,29.34 116.87,28.94 116.87,28.33 116.63,28.1 116.63,27.21 v3(116.41,26.98) ; v3(84.76,26.95) 85.08,26.95 85.13,27 R4655.1 85.88,26.89 R4658.1 86.68,25.66 86.51,25.49 v1(86.51,24.87) 88.03,24.87 88.93,25.77 Q12.2
FM_P3V3_E1S_3_EN_D: length 4.2
  BOTTOM w0.109: R4657.2 R4655.2 86.68,26.9 v1(87.83,25.76) 88.28,26.2 Q12.3
FM_P3V3_E1S_3_EN_G: length 4.8
  BOTTOM w0.109: R4656.1 91.37,26.19 v1(90.89,26.66) 90.08,27.48 90.08,27.84 89.54,28.37 89.03,28.37 88.93,28.48 Q12.5
FM_P3V3_E1S_3_EN_R_G: length 5.2
  BOTTOM w0.109: Q12.6 89.58,28.87 90.51,27.93 v1(90.89,27.93) 91.53,27.93 91.62,28.02 R4654.2 C322.1 92.06,26.99 R4656.2
FM_P3V3_E1S_3_R_EN: length 10.4
  TOP w0.109: U35.M4 v4(123.42,35.3)
  BOTTOM w0.109: R728.1 117.24,29.79 117.37,29.92 117.37,30.24 117.45,30.51 117.69,30.87 117.73,30.87 118.05,31.19 118.3,31.19 v1(118.89,31.78) 119.71,32.12 120.89,33.31 121.26,33.31 121.41,33.46 121.41,33.98 121.73,34.11 122.89,34.11 123.01,34.23 123.01,34.9 v4(123.42,35.3)
FM_P3V3_E1S_3_SW_EN: length 47.4
  TOP w0.109: U9.2 92.08,33.14 v3(91.31,33.91) 91.19,34.04 R199.2 ; R501.1 95.26,24.3 R460.2 95.8,25.15 95.38,25.58 v3(94.87,25.58) 94.77,25.58 93.58,26.76 U29.D2
  IN1 w0.124: v3(91.31,33.91) 89.27,35.95 88.4,35.95 86.94,34.49 v3(86.94,30.07)
  BOTTOM w0.109: R203.1 91.57,34.16 v3(91.31,33.91) ; R4657.1 85.64,27.67 v1(84.44,27.67) 84.03,27.67 83.33,26.98 83.33,26.22 85.39,24.16 88.01,24.16 88.69,24.84 94.76,24.84 94.87,24.95 v3(94.87,25.58) 94.87,28.26 94.32,28.81 92.08,28.81 91.78,28.5 90.9,28.5 90.32,29.08 90.32,29.92 90.17,30.07 v3(86.94,30.07)
FM_P3V3_E1S_EN_R: length 3.8
  TOP w0.109: U35.R9 v4(128.22,32.9)
  BOTTOM w0.109: v4(128.22,32.9) 128.31,32.81 128.31,31.04 R731.2
FM_P12V_E1S_0_EN: length 192
  TOP w0.109: v3(136.88,44.93) 137.11,44.7 137.11,42.61 138.1,40.22 138.1,39.37 137.34,38.61 R623.1
  IN1 w0.124: v3(136.88,44.93) 137.41,45.47 137.41,48.92 136.88,49.45 136.88,50.63 137.19,50.94 137.19,53.76 136.62,54.33 136.62,60.79 135.7,61.71 120.89,61.71 120.4,61.21 v3(120.4,61.01) ; v3(106.22,38.67) 102.7,42.19 96.8,42.19 96.12,42.88 94.81,42.88 92.17,45.52 86.02,45.52 83.27,42.77 79.04,42.77 77.83,41.55 74.9,41.55 73.25,39.9 73.25,37.92 70.61,35.28 67.03,35.28 62.87,39.45 60.88,39.45 58.04,42.29 56.54,42.29 55.65,43.18 48.47,43.18 45.72,45.93 40.87,45.93 39.98,46.81 32.84,46.81 30.3,44.27 23.7,44.27 21.84,46.13 v3(21.84,58.75)
  BOTTOM w0.109: v3(106.22,38.67) 106.86,38.03 108.34,38.03 109.32,39.01 109.32,44.47 111.09,46.24 111.09,46.55 114.6,50.07 114.6,51.61 116.61,53.62 117.37,54.13 118.14,54.89 118.6,56.01 118.86,56.65 118.87,56.65 118.9,56.74 119.59,57.42 120.04,57.42 120.15,57.53 120.15,58.44 119.88,58.71 119.88,60.5 v3(120.4,61.01) ; v3(21.84,58.75) 22.23,58.75 22.76,58.22 22.76,56.13 23.25,55.65 R4622.1 R4635.1 22.4,54.31 22.28,54.43 21.39,54.43 21.23,54.28 Q5.2
FM_P12V_E1S_0_EN_D: length 4.7
  BOTTOM w0.109: R4635.2 23.25,53.51 R4619.2 v1(23.25,52.08) 21.88,53.44 Q5.3
FM_P12V_E1S_0_EN_G: length 7.8
  BOTTOM w0.109: R4620.1 18.93,54.68 18.68,54.93 v1(18.68,55.83) 19.45,55.83 19.87,55.41 19.87,52.63 20.12,52.37 21.13,52.37 21.23,52.27 Q5.5
FM_P12V_E1S_0_EN_R_G: length 5.6
  BOTTOM w0.109: Q5.6 20.58,50.81 20.28,50.51 19.44,50.51 19.33,50.62 v1(19.33,50.65) 19.33,51.16 19.32,51.17 19.32,51.44 19.3,51.46 19.3,51.87 R4621.2 C315.1 19.32,52.86 19.33,52.86 R4620.2
FM_P12V_E1S_0_R_EN: length 4.2
  TOP w0.109: R623.2 135.74,38.74 v4(135.31,39.17) 135,39.48 135,40.6 134.31,41.3 U35.E16
FM_P12V_E1S_0_SW_EN: length 39.9
  TOP w0.109: R439.2 R440.1 14.86,58.31 14.86,57.15 15.46,56.55 v3(16.42,56.55) 16.9,56.55 17.21,56.86 U22.D2 ; U3.2 23.54,59.68 v3(23.33,59.9) 23.95,60.51 R170.2 23.95,61.51 R175.1
  IN1 w0.124: v3(19.3,49.1) 21.29,51.08 21.29,59 21.77,59.49 22.92,59.49 v3(23.33,59.9) 17.38,59.9 16.97,59.48 16.97,57.1 v3(16.42,56.55)
  BOTTOM w0.109: v3(19.3,49.1) 22.58,49.1 24.05,50.57 R4619.1
FM_P12V_E1S_1_EN: length 130.2
  IN1 w0.124: v3(49.07,53.01) 49.17,53.11 49.17,56.13 48.9,56.41 47.37,56.41 47.24,56.29 47.24,45.62 48.72,44.15 56.13,44.15 57.22,45.24 63.17,45.24 67.72,49.78 70.21,49.78 71.91,48.08 71.91,46.08 74.06,43.92 74.06,43.92 74.12,43.87 81.01,43.87 82.46,45.32 82.98,45.32 83.59,44.72 84.01,44.72 85.67,46.38 92.53,46.38 95.17,43.74 96.63,43.74 97.32,43.05 103.48,43.05 105.85,40.68 108.44,40.68 109.74,39.39 109.74,38.78 110.26,38.25 111,38.25 112.09,39.34 113.47,39.34 115.66,41.54 118.15,41.54 120.02,39.67 123.64,39.67 124.42,38.89 126.9,38.89 127.48,38.3 127.48,36.78 127.76,36.5 133.78,36.5 133.96,36.68 v3(134.13,36.68)
  BOTTOM w0.109: v3(134.13,36.68) 134.39,36.93 135.45,36.93 136.39,37.87 R624.1 ; Q6.2 44.91,53.6 45.2,53.9 v1(46.27,53.9) 46.27,52.38 46.46,52.2 47.26,52.2 R4636.1 R4626.1 48.18,52.68 48.51,53.01 v3(49.07,53.01)
FM_P12V_E1S_1_EN_D: length 6.3
  BOTTOM w0.109: 46.25,49.3 46.89,49.95 R4623.2 R4636.2 ; 46.25,49.3 46.25,51.5 45.56,52.19 Q6.3 ; 46.25,49.3 v1(46.24,49.29)
FM_P12V_E1S_1_EN_G: length 7.6
  BOTTOM w0.109: R4624.1 41.79,54.74 42.14,55.09 43.18,55.09 43.74,54.53 v1(43.74,54.21) 43.74,51.47 43.9,51.31 44.6,51.31 44.91,51 Q6.5
FM_P12V_E1S_1_EN_R_G: length 5.9
  BOTTOM w0.109: Q6.6 44.26,50.1 44.12,49.96 43.71,49.96 v1(42.81,50.87) 42.59,51.09 R4625.2 C316.1 R4624.2
FM_P12V_E1S_1_R_EN: length 6.5
  TOP w0.109: U35.G14 v4(132.22,40.1)
  BOTTOM w0.109: R624.2 136.65,39.73 136.54,39.83 v1(136.42,39.83) 134.72,39.83 134.07,40.49 132.6,40.49 v4(132.22,40.1)
FM_P12V_E1S_1_SW_EN: length 29.1
  TOP w0.109: R173.2 R443.1 39.62,57.3 39.62,56.26 40.23,55.66 v3(41.18,55.66) 41.98,56.45 U23.D2 ; U4.2 48.31,59.13 48.32,59.14 v3(48.32,59.18) 48.32,59.58 48.71,59.98 R442.2 48.69,60.42 R176.1
  IN1 w0.124: v3(48.32,59.18) 46.86,57.73 46.86,56.82 45.49,55.45 43.89,55.45 43.68,55.66 v3(41.18,55.66)
  IN2 w0.124: v3(49.03,52.25) 48.44,52.84 48.44,54.43 49.15,55.14 49.15,56.18 48.32,57.01 v3(48.32,59.18)
  BOTTOM w0.109: R4623.1 48.82,50.85 49.03,51.06 v3(49.03,52.25)
FM_P12V_E1S_2_EN: length 93.3
  TOP w0.109: R625.1 136.54,37.23 136.4,37.08 135.51,37.08 134.64,37.95 134.4,38.54 v3(134.01,38.93)
  IN1 w0.124: v3(73.46,59.44) 72.83,58.81 72.83,46.53 74.57,44.78 80.65,44.78 82.07,46.21 82.84,46.21 83.39,46.75 95.23,46.75 98.49,43.49 103.57,43.49 106,41.06 108.6,41.06 110.14,39.52 110.14,38.91 110.42,38.63 110.85,38.63 112.02,39.8 113.36,39.8 115.49,41.93 118.48,41.93 119.93,40.48 123.75,40.48 124.5,39.73 127.25,39.73 128.07,38.91 130.58,38.91 130.91,38.58 133.66,38.58 v3(134.01,38.93)
  BOTTOM w0.109: v3(73.46,59.44) 73.46,58.77 73.99,58.24 v1(73.99,57.78) 73.99,56.25 R4630.1 R4637.1 72.39,55.98 71.98,56.39 Q7.2
FM_P12V_E1S_2_EN_D: length 4.6
  BOTTOM w0.109: Q7.3 71.33,56.12 71.48,55.98 R4627.2 71.62,55.57 72.39,54.79 R4637.2 72.39,54.17 73.09,53.47 v1(73.22,53.47)
FM_P12V_E1S_2_EN_G: length 4.2
  BOTTOM w0.109: R4628.1 69.52,59.82 v1(69.77,60.06) 70.23,59.6 71.87,59.6 71.98,59.49 Q7.5
FM_P12V_E1S_2_EN_R_G: length 8.5
  BOTTOM w0.109: R4629.2 C317.1 67.8,59.6 R4628.2 67.8,59.88 68.54,60.62 70.32,60.62 70.6,60.34 v1(71.56,60.34) 72.12,60.34 72.63,59.83 Q7.6
FM_P12V_E1S_2_R_EN: length 4.5
  TOP w0.109: U35.F16 133.98,40.5 134.25,40.23 134.25,39.8 v4(134.04,39.59) 134.5,39.13 134.91,38.13 135.45,37.59 R625.2
FM_P12V_E1S_2_SW_EN: length 26.1
  TOP w0.109: U24.D2 67.5,56 67.19,55.68 v3(66.71,55.68) 65.76,55.68 64.67,56.76 R447.1 R178.2 ; U5.2 73.83,58.95 73.94,59.05 73.94,59.44 v3(74.14,59.64) 74.14,60.08 74.24,60.18 R446.2 74.22,60.45 R183.1
  IN1 w0.124: v3(66.71,55.68) 66.98,55.95 66.98,59.66 67.51,60.19 74.01,60.19 74.14,60.07 v3(74.14,59.64)
  BOTTOM w0.109: R4627.1 70.86,55.38 70.86,55.72 70.38,56.21 66.82,56.21 66.71,56.1 v3(66.71,55.68)
FM_P12V_E1S_3_EN: length 58.2
  TOP w0.109: v3(110.13,46) 110.84,46 111.13,45.71 113.15,45.71 114.01,45.35 114.58,44.97 115.78,43.77 115.78,43.45 115.85,43.38 115.85,42.24 115.78,42.05 115.78,41.97 115.72,41.91 115.23,40.73 113.97,39.47 113.97,36.2 114.35,35.81 114.94,35.57 115.45,35.57 115.56,35.46 v3(115.56,35.21)
  IN1 w0.124: v3(110.13,46) 109.8,46.33 108.87,46.33 107.93,45.39 106.63,45.39 105.66,44.42 100.13,44.42 97.87,46.69 97.87,52.73 98.3,53.16 98.3,58.98 98.04,59.23 97,59.23 v3(96.93,59.16)
  BOTTOM w0.109: Q8.2 97.9,52.55 R4638.1 R4634.1 98.15,53.45 98.6,53.9 98.6,56.08 98.7,56.18 98.7,58.71 98.18,59.23 97,59.23 v3(96.93,59.16) ; v3(115.56,35.21) 115.56,35.15 R727.1
FM_P12V_E1S_3_EN_D: length 5.9
  BOTTOM w0.109: R4638.2 98.15,51.5 R4631.2 98.15,50.74 97.55,50.13 v1(97.32,50.13) 97.2,50.25 97.2,51.71 97.01,51.9 Q8.3
FM_P12V_E1S_3_EN_G: length 2.7
  BOTTOM w0.109: Q8.5 92.84,52.55 v1(92.73,52.66) 92.35,53.04 R4632.1
FM_P12V_E1S_3_EN_R_G: length 7.4
  BOTTOM w0.109: C318.1 89.77,51.97 89.63,52.12 v1(89.63,52.4) 89.63,52.74 89.92,53.04 R4632.2 90.79,53.3 R4633.2 92.39,54.1 93.29,53.2 Q8.6
FM_P12V_E1S_3_R_EN: length 9
  TOP w0.109: U35.L3 v4(122.62,36.1)
  BOTTOM w0.109: R727.2 116.79,33.47 116.79,34.13 116.9,34.24 117.42,34.24 117.75,33.91 119.3,33.91 121.06,34.64 121.76,34.64 122.25,35.13 122.25,35.76 122.59,36.1 v4(122.62,36.1)
FM_P12V_E1S_3_SW_EN: length 27.2
  TOP w0.109: R450.2 R451.1 90.15,56.92 91.23,55.83 v3(92.19,55.83) 92.66,55.83 92.98,56.15 U25.D2 ; U6.2 v3(99.31,59.32) 99.33,59.33 99.33,59.7 99.71,60.08 R181.2 99.69,60.6 R184.1
  IN2 w0.124: v3(92.19,55.83) 92.35,56 92.35,58.24 93.87,59.76 98.87,59.76 v3(99.31,59.32)
  BOTTOM w0.109: v3(99.31,59.32) 99.31,58.37 100.19,57.5 100.19,53.07 99.36,52.25 99.36,51.8 R4631.1
FM_P12V_EDGE_EN: length 156.6
  TOP w0.109: R729.1 127.38,26.52 127.05,26.19 123.93,26.19 v3(123.83,26.29) ; v3(5.57,28.75) 5.57,27.62 Q4.G
  IN1 w0.124: v3(5.57,28.75) 6.4,27.93 7.78,27.93 8.39,28.54 8.39,30.58 10.85,33.04 10.85,35.23 11.35,35.74 13.74,35.74 15.38,34.09 18.23,34.09 18.5,33.82 21.5,33.82 27.55,27.77 29.6,27.77 29.74,27.91 31.29,27.91 31.38,27.83 34.84,27.83 36.27,29.26 36.27,29.72 35.18,30.81 35.18,31.7 36.3,32.82 42.42,32.82 43.86,31.38 48.41,31.38 52.17,27.61 54.26,27.61 55.04,28.4 58.35,28.4 59.73,27.02 62.62,27.02 63.27,26.36 63.27,24.36 63.88,23.75 65.86,22.94 71.17,22.94 73.08,24.84 76.99,24.84 80.34,28.2 82.11,28.2 83.05,27.26 83.05,26.58 83.69,25.94 85.08,25.94 90.54,31.4 94.31,31.4 95.22,30.49 100.55,30.49 103.43,27.61 103.99,27.61 104.48,28.1 108.62,28.1 111.34,25.37 111.34,24.19 111.55,23.98 113.11,23.98 113.38,24.25 117.09,24.25 117.84,25 119.04,25 119.26,24.79 121.69,24.79 122.07,25.17 122.71,25.17 v3(123.83,26.29)
  BOTTOM w0.109: C302.1 5.1,28.28 v3(5.57,28.75)
FM_P12V_EDGE_EN_D: length 5.9
  TOP w0.109: R531.1 v2(3.68,24.64) 3.28,25.04 2.02,25.04 R530.1 1.55,25.68 1.87,26 Q3.D
FM_P12V_EDGE_EN_G: length 3.9
  TOP w0.109: Q3.G v3(2.89,26.7)
  BOTTOM w0.109: R4671.2 2.56,26.37 v3(2.89,26.7) 2.56,27.03 C303.1 2.56,28.47 v1(2.68,28.59)
FM_P12V_EDGE_EN_R: length 6.1
  TOP w0.109: U35.T10 128.62,31.95 128.42,31.75 v4(127.9,31.75) 127.9,30.7 127.38,30.18 R730.2 127.74,30.12 127.89,29.97 127.89,28.21 127.76,28.09 R729.2
FM_P12V_EDGE_EN_R_G: length 9.6
  TOP w0.109: R529.2 7.9,23.68 v2(7.72,23.5) 7.14,24.08 7.14,25.16 6.31,25.98 Q4.D 4.48,25.5 v3(3.66,25.5)
  BOTTOM w0.109: R4671.1 1.76,25.61 1.87,25.5 v3(3.66,25.5)
FM_POWER_EN: length 145.4
  TOP w0.109: v3(10.36,13.56) 10.36,13.39 10.41,13.34 R2.1 ; U35.L2 v4(121.82,36.1) 120.85,36.1 120,35.26 120,33.65 119.81,33.19 v4(119.82,33.17) ; v3(116.88,31.1) 116.87,31.1 116.54,31.1 116.43,30.99 116.43,30.61 115.47,29.65 115.47,25.87 115.93,24.77 v3(115.93,22.23)
  IN1 w0.124: v3(115.93,22.23) 115.93,20.38 114.74,19.2 111.47,19.2 111.13,18.86 110.59,18.86 109.2,20.25 104.67,20.25 100.12,24.8 96.79,24.8 96.56,25.03 89.42,25.03 85.52,21.13 74.54,21.13 71.45,18.03 63.22,18.03 60.8,20.46 53.96,20.46 48.5,15 42.83,15 38.29,19.53 26.24,19.53 23.88,17.17 23.88,13.49 20.73,10.34 15.39,10.34 14.52,11.21 12.71,11.21 v3(10.36,13.56)
  BOTTOM w0.109: v4(119.82,33.17) 119.68,33.04 119.68,32.69 119.42,32.44 118.64,32.28 118.44,32.12 118.31,31.79 118.07,31.56 116.98,31.56 116.87,31.45 116.87,31.1 v3(116.88,31.1)
FM_POWER_EN_R: length 10.9
  TOP w0.109: GF1.OCP_B2 8.26,3.94 9.29,4.97 9.29,10.18 v2(9.88,10.77) 10.41,11.3 R2.2
FM_PRSNT_E1S_0_N: length 122.6
  TOP w0.109: v3(34.92,36.83) 34.92,36.96 33.99,37.89 J4.A12 ; R555.2 v3(130.43,25.89)
  IN2 w0.124: v3(34.92,36.83) 34.92,36.09 35.94,35.08 47.29,35.08 47.88,34.5 47.88,27.45 48.25,27.08 48.25,26.87 61.84,13.29 86.59,13.29 87.19,12.69 96.19,12.69 97.93,14.43 107.65,14.43 108.08,14 115.94,14 117.23,15.28 117.23,18.06 119.9,20.73 121.95,20.73 122.57,20.12 125.37,20.12 130.43,25.18 v3(130.43,25.89)
FM_PRSNT_E1S_0_R_N: length 6.7
  TOP w0.109: U35.R13 131.44,32.87 131.44,31.6 130.43,30.58 R571.2 130.79,30.12 130.94,29.97 130.94,28.21 130.81,28.09 R555.1
FM_PRSNT_E1S_1_N: length 105.7
  TOP w0.109: v3(59.94,36.96) 59.94,37.75 59.59,38.1 58.93,38.1 58.72,37.9 J5.A12 ; R556.2 v3(131.44,26.39) ; v3(115.96,30.83) 115.1,29.96 115.1,26.27 113.21,24.37 113.21,21.51 v3(113.31,21.41)
  IN2 w0.124: v3(59.94,36.96) 59.94,36.27 61.89,34.32 61.89,34.01 63.06,32.85 63.87,32.04 63.87,31.83 65.79,29.91 67.18,29.91 69.79,27.3 79.88,27.3 80.64,28.07 83.03,28.07 83.66,27.43 85.69,27.43 87.07,28.01 87.57,28.51 91.63,28.51 92.03,28.91 93.73,28.91 95.78,30.96 99.51,30.96 101.52,32.97 105.97,32.97 106.08,32.85 109.18,32.85 109.42,32.61 109.42,31.54 109.94,31.03 115.38,31.03 115.58,30.83 v3(115.96,30.83)
  BOTTOM w0.109: v3(131.44,26.39) 131.44,23.62 131.1,23.27 131.1,21.63 130.15,20.68 129.54,20.68 128.77,19.91 126.7,19.91 126.04,20.56 122.7,20.56 122.13,21.13 121.23,21.13 119.7,19.59 118.73,19.59 117.58,18.44 115.8,18.44 113.39,20.85 113.39,21.34 v3(113.31,21.41)
